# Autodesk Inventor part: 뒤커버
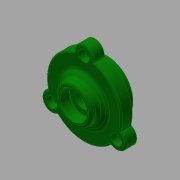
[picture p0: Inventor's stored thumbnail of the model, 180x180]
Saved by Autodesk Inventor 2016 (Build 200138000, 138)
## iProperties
Created: 2016-05
Part Number: 뒤커버
Document SubType Name: Modeling
Designer: mduedu
Density: 2.71 g/cm^3
Material: 알루미늄 6061
Appearance: 진녹색
Author: mduedu
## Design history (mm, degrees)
sketch "스케치1"
  geometry: C1 r 20 at (0, 0); C2 r 27.5 at (0, 0); 1 further point
  constraints: 2 centre point, 2 coincident
  dimensions: "d33" = 55 diameter of C2; "d34" = 40 diameter of C1
extrude "돌출1" new body sketch "스케치1" distance "d0" = 8; taper "d1" = 0 deg
extrude "돌출2" join sketch "스케치1" distance "d2" = 8; taper "d3" = 0 deg; dims "d35" = 9, "d36" = 0
sketch "스케치5"
  geometry: L1 (-27.5, 8)-(27.5, 8) reference; L2 (0, 0)-(0, 15); L3 (-27.5, 0)-(27.5, 0) reference; L4 (17.5, 8)-(0, 8); A1 r 25.375 centre (0, -10.375) between (17.5, 8) and (0, 15)
  constraints: 4 end point, 3 point on line, 2 point on circle, 1 centre point, 1 midpoint, 1 perpendicular
  dimensions: "d37" = 17.5 distance from line of L2 L4.start; "d39" = 7 distance from line of L1 L2.end
revolve "회전2" sketch "스케치5" stored, may be unused: angle "d40" = 90 deg
node "작업 평면1"
sketch "스케치6"
  geometry: C1 r 13.5 at (0, 0); 1 further point
  constraints: 1 centre point, 1 coincident
  dimensions: "d42" = 27 diameter of C1
extrude "돌출4" join sketch "스케치6" stored distance "d43" = 10; taper "d44" = 0 deg
sketch "스케치4"
  geometry: L1 (0, -9)-(0, 16); L2 (-15, -9)-(-15, 0); L3 (-15, 0)-(-10, 0); L4 (-10, 0)-(-10, 3); L5 (-10, 3)-(-6, 3); L6 (-6, 3)-(-6, 8.6); L7 (-6, 8.6)-(-10, 8.6); L8 (-10, 8.6)-(-10, 16); L9 (20, -9)-(-20, -9) reference; L10 (-13.5, 16)-(13.5, 16) reference; 1 further point
  constraints: 16 end point, 6 parallel, 3 point on line, 2 midpoint, 1 perpendicular, 1 vertical
  dimensions: "d15" = 30 diameter of L2 L1; "d16" = 20 diameter of L8 L1; "d18" = 9 distance of L2.start L2.end; "d19" = 3 distance of L3.end L4.end; "d20" = 20 diameter of L4 L1; "d21" = 12 diameter of L6 L1; "d45" = 7.4 distance of L7.end L8.end
revolve "회전1" sketch "스케치4" stored, may be unused: angle "d22" = 90 deg
fillet "모깎기2" dims "d23" = 3
fillet "모깎기3" dims "d24" = 0.3
chamfer "모따기2" distance "d46" = 1; stored, may be unused: second distance "d47" = 2, angle "d48" = 45 deg
fillet "모깎기4" dims "d49" = 3
fillet "모깎기5" dims "d50" = 2
sketch "스케치7"
  geometry: C1 r 7 at (0, 27.5); 2 further points
  constraints: 3 vertical alignment, 1 centre point, 2 other
  dimensions: "d54" = 14 diameter of C1
extrude "돌출5" join sketch "스케치7" stored distance "d55" = 10; taper "d56" = 0 deg
fillet "모깎기6" dims "d57" = 1
fillet "모깎기7" dims "d61" = 1
sketch "스케치8" dims "d62" = 55 (derived)
  geometry: C1 r 18.661 at (0, 0) reference; A1 r 2 centre (-7.999, 27.355) between (-7.437, 25.435) and (-5.999, 27.391) reference; A2 r 26.5 centre (0, 0) between (-7.437, 25.435) and (-25.746, -6.277) reference; A3 r 2 centre (-27.689, -6.75) between (-26.721, -8.5) and (-25.746, -6.277) reference; A4 r 6 centre (-23.816, -13.75) between (-26.721, -8.5) and (-20.722, -18.891) reference; A5 r 2 centre (-19.69, -20.604) between (-18.309, -19.158) and (-20.722, -18.891) reference; A6 r 26.5 centre (0, 0) between (-18.309, -19.158) and (18.309, -19.158) reference; A7 r 2 centre (19.69, -20.604) between (20.722, -18.891) and (18.309, -19.158) reference; A8 r 6 centre (23.816, -13.75) between (20.722, -18.891) and (26.721, -8.5) reference; A9 r 2 centre (27.689, -6.75) between (25.746, -6.277) and (26.721, -8.5) reference; A10 r 26.5 centre (0, 0) between (25.746, -6.277) and (7.437, 25.435) reference; A11 r 2 centre (7.999, 27.355) between (5.999, 27.391) and (7.437, 25.435) reference; A12 r 6 centre (0, 27.5) between (5.999, 27.391) and (-5.999, 27.391) reference; 4 further points
  constraints: 2 coincident, 1 vertical alignment, 6 other
  dimensions: "d65" = 360 deg dimension on A2.centre point (0, 27.5) (derived)
sketch "스케치9"
  geometry: 3 further points
  constraints: 3 other
hole "구멍2" sketch "스케치9" at (-23.816, -13.75), (23.816, -13.75), (0, 27.5) diameter "d67" = 4.5; stored, may be unused: countersink angle "d71" = 90 deg, drill point angle "d73" = 0 deg; dims "d68" = 6, "d69" = 8, "d70" = 4.6, "d72" = 8
chamfer "모따기3" distance "d76" = 0.7; stored, may be unused: second distance "d77" = 2, angle "d78" = 30 deg
node "솔리드1"
pattern_circular "원형 패턴1" dims angle "d59" = 360 deg
other parameters: "d41" = 8
